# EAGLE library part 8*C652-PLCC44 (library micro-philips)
CMOS single-chip 8-bit Microcontroller
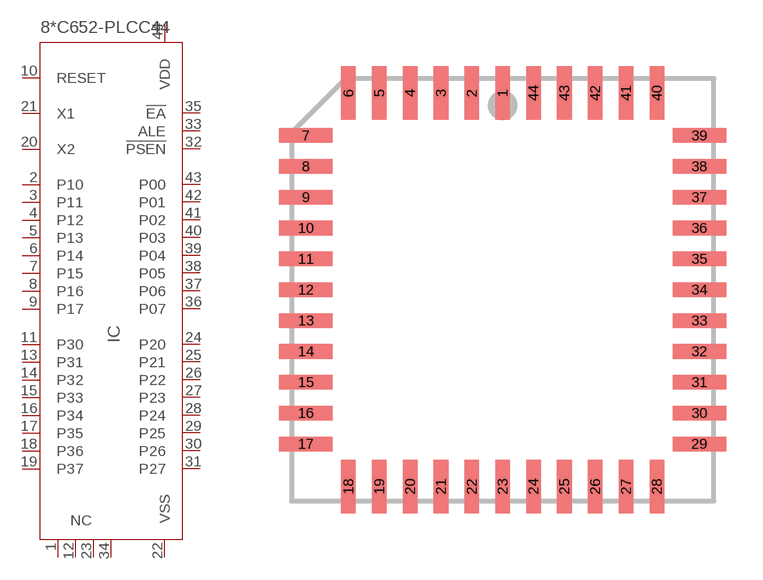
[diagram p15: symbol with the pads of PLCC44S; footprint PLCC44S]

Designator prefix IC

## 80C652-PLCC44 (OC_FARNELL: unknown; OC_NEWARK: unknown), 83C652-PLCC44 (OC_FARNELL: unknown; OC_NEWARK: unknown)  [PLCC44S]
1  NC
2  P10
3  P11
4  P12
5  P13
6  P14
7  P15
8  P16
9  P17
10  RESET
11  P30
12  NC
13  P31
14  P32
15  P33
16  P34
17  P35
18  P36
19  P37
20  X2  out
21  X1  in
22  VSS  pwr
23  NC
24  P20
25  P21
26  P22
27  P23
28  P24
29  P25
30  P26
31  P27
32  !PSEN  out
33  ALE  out
34  NC
35  !EA  in
36  P07
37  P06
38  P05
39  P04
40  P03
41  P02
42  P01
43  P00
44  VDD  pwr

## Footprint PLCC44S (pad centres in mm)
PLASTIC LEADED CHIP CARRIER square
smd 0.6 x 2.2: 1 0,8.1; 2 -1.27,8.1; 3 -2.54,8.1; 4 -3.81,8.1; 5 -5.08,8.1; 6 -6.35,8.1; 18 -6.35,-8.1; 19 -5.08,-8.1; 20 -3.81,-8.1; 21 -2.54,-8.1; 22 -1.27,-8.1; 23 0,-8.1; 24 1.27,-8.1; 25 2.54,-8.1; 26 3.81,-8.1; 27 5.08,-8.1; 28 6.35,-8.1; 40 6.35,8.1; 41 5.08,8.1; 42 3.81,8.1; 43 2.54,8.1; 44 1.27,8.1
smd 2.2 x 0.6: 7 -8.1,6.35; 8 -8.1,5.08; 9 -8.1,3.81; 10 -8.1,2.54; 11 -8.1,1.27; 12 -8.1,0; 13 -8.1,-1.27; 14 -8.1,-2.54; 15 -8.1,-3.81; 16 -8.1,-5.08; 17 -8.1,-6.35; 29 8.1,-6.35; 30 8.1,-5.08; 31 8.1,-3.81; 32 8.1,-2.54; 33 8.1,-1.27; 34 8.1,0; 35 8.1,1.27; 36 8.1,2.54; 37 8.1,3.81; 38 8.1,5.08; 39 8.1,6.35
